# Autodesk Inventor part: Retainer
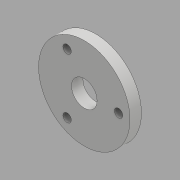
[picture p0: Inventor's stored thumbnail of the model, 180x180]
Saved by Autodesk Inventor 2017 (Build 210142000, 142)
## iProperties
Created: 2016-05
Part Number: Retainer
Material: Generic
Document SubType Name: Modeling
Designer: CADCIM
Density: 1 g/cm^3
Appearance: Default
Author: CADCIM
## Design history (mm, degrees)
sketch "Sketch1"
  geometry: C1 r 100 at (0, 0); 1 further point
  constraints: 1 centre point, 1 coincident
  dimensions: "d0" = 200 diameter of C1
extrude "Extrusion1" new body sketch "Sketch1" distance "d1" = 25; taper "d2" = 0 deg
sketch "Sketch2"
  geometry: 1 further point
sketch "Sketch3" dims "d3" = 150
  geometry: L1 (0, 0)-(102.916, 0); 2 further points
  constraints: 2 end point, 1 coincident, 1 horizontal, 1 horizontal alignment, 1 point on line, 2 other
hole "Hole1" sketch "Sketch3" at (75, 0) diameter "d4" = 18.376; stored, may be unused: countersink angle "d8" = 90 deg, drill point angle "d10" = 118 deg; dims "d5" = 40, "d6" = 4, "d7" = 2, "d9" = 47.3
pattern_circular "Circular Pattern1" dims angle "d12" = 360 deg
sketch "Sketch4"
  geometry: C1 r 28 at (0, 0); 1 further point
  constraints: 1 centre point, 1 coincident
  dimensions: "d14" = 56 diameter of C1
extrude "Extrusion2" cut sketch "Sketch4" distance "d15" = 25; taper "d16" = 0 deg
body "Solid1"
